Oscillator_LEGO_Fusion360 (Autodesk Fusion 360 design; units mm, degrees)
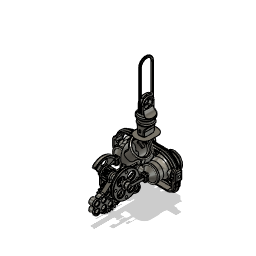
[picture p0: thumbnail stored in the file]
parameter "Piston_Stroke" = 13
parameter "Piston_Radius" = 6
named bodies: "Piston_Washer", "Cylinder_Ring", "Crank_Deco", "Cylinder", "Piston", "Cylinder_Front", "Pin", "Flywheel_Simpler", "Crank_Right", "Frame_2Cyl_Reinforced", "Gear_32T", "Base_Lego_Max", "Base_Lego_Min", "Spur_Gear_16", "OneCylinder_Lid", "Frame_1Cyl_Reinforced", "Crank_Right_Gear", "Flywheel_Heavy", "Key_Smaller", "Key_Smaller_Clip", "KeyClip"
